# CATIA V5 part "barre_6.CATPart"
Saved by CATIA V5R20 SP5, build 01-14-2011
Part number: barre_6
Publications: "diamètre trou oblong 'd'", "diamètre trou oblong 'm'", "diamètre pivot en H"
Bounding box of the stored display mesh (mm): x 12 to 18, y -56 to -29.216, z 65.601 to 246.824
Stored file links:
  M:\EU_thinkMotion\IAO_2010\iao\IAO_MMS_Groupe2\IAO_MMS_Groupe2\sdubois\sdubois\sdubois\IAO_mecanisme\barre_6.CATPart
  M:\EU_thinkMotion\IAO_2010\iao\IAO_MMS_Groupe2\IAO_MMS_Groupe2\sdubois\sdubois\sdubois\IAO_mecanisme\assembage final.CATProduct
  M:\EU_thinkMotion\IAO_2010\iao\IAO_MMS_Groupe2\IAO_MMS_Groupe2\sdubois\sdubois\sdubois\IAO_mecanisme\squelette_6.CATPart
  M:\EU_thinkMotion\IAO_2010\iao\IAO_MMS_Groupe2\IAO_MMS_Groupe2\sdubois\sdubois\sdubois\IAO_mecanisme\bati_0.CATPart
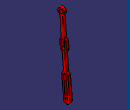
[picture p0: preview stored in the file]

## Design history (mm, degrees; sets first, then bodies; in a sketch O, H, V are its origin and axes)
Parameters
  `diamètre trou oblong 'd'` = 6 mm
  `diamètre trou oblong 'm'` = 8 mm
  `diamètre pivot en H` = 8 mm
External parameters (linked from other documents)
  External.largeur_barre = 6 mm
Set1
  Plane1: linked copy from another document
  Plane2: linked copy from another document
  Point1: linked copy from another document
  Point2: linked copy from another document
  Plane3: linked copy from another document
  Plane4: linked copy from another document
  Point3 to Point7: linked copy from another document
  Plane5 to Plane7: linked copy from another document
  DatumSurface1: linked copy from another document
  Line1 to Line5: linked copy from another document
Body1 (main body)
  Sketch1 on Plane1, origin (12, 0, 0), H (0, 1, 0), V (0, 0, 1)
    line L1 (-39.207, 72.2588) -> (-51.9913, 239.7717)
    point P1 (-39.207, 72.2588)
    point P2 (-51.9913, 239.7717)
    line L2 (-33.2244, 72.7154) -> (-46.0087, 240.2283)
    point P3 (-33.2244, 72.7154)
    point P4 (-46.0087, 240.2283)
    line L3 (-51.9913, 239.7717) -> (-46.0087, 240.2283)
    point P5 (-51.9913, 239.7717)
    point P6 (-46.0087, 240.2283)
    point P7 (-39.207, 72.2588)
    reference intersected line E1 through (-30.489, -2.55) direction (0.0761, -0.9971) from Plane2
    reference intersected line E2 through (-30.489, -2.55) direction (0.0761, -0.9971) from Plane2
    reference projected point E3 (-46.6645, 169.9747) from Point1
    reference projected point E4 (-40.6819, 170.4313) from Point2
    reference intersected line E5 through (-6.293, 74.7708) direction (-0.9971, -0.0761) from Plane3
    reference intersected line E6 through (-6.293, 74.7708) direction (-0.9971, -0.0761) from Plane3
    reference intersected line E7 through (-20.3417, 242.1871) direction (-0.9971, -0.0761) from Plane4
    reference intersected line E8 through (-20.3417, 242.1871) direction (-0.9971, -0.0761) from Plane4
    line L4 (-39.207, 72.2588) -> (-33.2244, 72.7154)
    point P8 (-39.207, 72.2588)
    point P9 (-33.2244, 72.7154)
    distance L1 E3 = 0
    distance L2 E4 = 0
    distance P1 E5 = 0
    distance P3 E6 = 0
    distance P2 E7 = 0
    distance P4 E8 = 0
    distance P5 P2 = 0
    distance P6 P4 = 0
    distance P1 P7 = 0
    distance P8 P1 = 0
    distance P9 P3 = 0
    parallelism: L1 E1, L2 E2
  Sketch2 on Plane1, origin (12, 0, 0), H (0, 1, 0), V (0, 0, 1)
    circle A1 centre (-36.2157, 72.4871) radius 7
    point P1 (-36.2157, 72.4871)
    circle A2 centre (-43.6732, 170.203) radius 7
    point P2 (-43.6732, 170.203)
    circle A3 centre (-39.8684, 120.3479) radius 7
    point P3 (-39.8684, 120.3479)
    circle A4 centre (-44.7386, 184.1624) radius 7
    point P4 (-44.7386, 184.1624)
    reference projected point E1 (-36.2157, 72.4871) from Point3
    reference projected point E2 (-39.8684, 120.3479) from Point4
    reference projected point E3 (-43.6732, 170.203) from Point5
    reference projected point E4 (-44.7386, 184.1624) from Point6
    circle A5 centre (-49, 240) radius 7
    point P5 (-49, 240)
    reference projected point E5 (-49, 240) from Point7
    distance P1 E1 = 0
    radius A1 = 7
    distance P3 E2 = 0
    radius A3 = 7
    distance E3 P2 = 0
    radius A2 = 7
    distance P4 E4 = 0
    radius A4 = 7
    distance P5 E5 = 0
    radius A5 = 7
  Sketch3 on Plane1, origin (12, 0, 0), H (0, 1, 0), V (0, 0, 1)
    line L1 (-50.6529, 169.6703) -> (-51.7183, 183.6297)
    point P1 (-50.6529, 169.6703)
    point P2 (-51.7183, 183.6297)
    reference intersected line E1 through (-30.489, -2.55) direction (0.0761, -0.9971) from Plane2
    reference projected circle E2 centre (-43.6732, 170.203) radius 7 from Sketch2.A2
    reference intersected line E3 through (-15.6588, 186.3817) direction (-0.9971, -0.0761) from Plane5
    reference intersected line E4 through (-14.4881, 172.4303) direction (-0.9971, -0.0761) from Plane6
    line L2 (-36.6935, 170.7356) -> (-37.7589, 184.6951)
    point P3 (-36.6935, 170.7356)
    point P4 (-37.7589, 184.6951)
    reference intersected line E5 through (-30.489, -2.55) direction (0.0761, -0.9971) from Plane2
    reference projected circle E6 centre (-44.7386, 184.1624) radius 7 from Sketch2.A4
    reference intersected line E7 through (-15.6588, 186.3817) direction (-0.9971, -0.0761) from Plane5
    reference intersected line E8 through (-14.4881, 172.4303) direction (-0.9971, -0.0761) from Plane6
    line L3 (-51.7183, 183.6297) -> (-37.7589, 184.6951)
    point P5 (-51.7183, 183.6297)
    point P6 (-37.7589, 184.6951)
    line L4 (-50.6529, 169.6703) -> (-36.6935, 170.7356)
    point P7 (-50.6529, 169.6703)
    point P8 (-36.6935, 170.7356)
    line L5 (-29.236, 73.0198) -> (-32.8887, 120.8806)
    point P9 (-29.236, 73.0198)
    point P10 (-32.8887, 120.8806)
    line L6 (-43.1954, 71.9544) -> (-46.8481, 119.8153)
    point P11 (-43.1954, 71.9544)
    point P12 (-46.8481, 119.8153)
    reference intersected line E9 through (-30.489, -2.55) direction (0.0761, -0.9971) from Plane2
    reference intersected line E10 through (-30.489, -2.55) direction (0.0761, -0.9971) from Plane2
    reference projected circle E11 centre (-39.8684, 120.3479) radius 7 from Sketch2.A3
    reference projected circle E12 centre (-39.8684, 120.3479) radius 7 from Sketch2.A3
    reference intersected line E13 through (-6.293, 74.7708) direction (-0.9971, -0.0761) from Plane3
    reference intersected line E14 through (-10.3069, 122.604) direction (-0.9971, -0.0761) from Plane7
    reference intersected line E15 through (-6.293, 74.7708) direction (-0.9971, -0.0761) from Plane3
    reference intersected line E16 through (-10.3069, 122.604) direction (-0.9971, -0.0761) from Plane7
    line L7 (-46.8481, 119.8153) -> (-32.8887, 120.8806)
    point P13 (-46.8481, 119.8153)
    point P14 (-32.8887, 120.8806)
    line L8 (-43.1954, 71.9544) -> (-29.236, 73.0198)
    point P15 (-43.1954, 71.9544)
    point P16 (-29.236, 73.0198)
    distance L1 E2 = 0
    distance P2 E3 = 0
    distance P1 E4 = 0
    distance E6 L2 = 0
    distance P4 E7 = 0
    distance P3 E8 = 0
    distance P5 P2 = 0
    distance P6 P4 = 0
    distance P7 P1 = 0
    distance P8 P3 = 0
    distance L5 E11 = 0
    distance L6 E12 = 0
    distance P11 E13 = 0
    distance P12 E14 = 0
    distance P9 E15 = 0
    distance P10 E16 = 0
    distance P13 P12 = 0
    distance P14 P10 = 0
    distance P15 P11 = 0
    distance P16 P9 = 0
    parallelism: L1 E1, L2 E5, L5 E9, L6 E10
  Pad1: profile Sketch1, direction (1, 0, 0), length 6 {= 3*External.largeur_barre -12mm}, opposite side length 0 {= 12mm-2*External.largeur_barre}
  Pad2: profile Sketch2, direction (-1, 0, 0), length 0 {= 12mm-2*External.largeur_barre}, opposite side length 6 {= 3*External.largeur_barre -12mm}
  Pad3: profile Sketch3, direction (1, 0, 0), length 6 {= 3*External.largeur_barre -12mm}, opposite side length 0 {= 12mm-2*External.largeur_barre}
  Sketch4 on face of Pad3, origin (18, 0, 0), H (0, 1, 0), V (0, 0, 1)
    construction line L1 (-39.8684, 120.3479) -> (-36.2157, 72.4871)
    point P1 (-39.8684, 120.3479)
    point P2 (-36.2157, 72.4871)
    line L2 (-36.8771, 120.5762) -> (-33.2244, 72.7154)
    line L3 (-39.207, 72.2588) -> (-42.8597, 120.1197)
    arc A1 centre (-36.2157, 72.4871) radius 3 from (-33.2244, 72.7154) to (-39.207, 72.2588) cw
    arc A2 centre (-39.8684, 120.3479) radius 3 from (-42.8597, 120.1197) to (-36.8771, 120.5762) cw
    reference projected point E1 (-39.8684, 120.3479) from Line1
    reference projected point E2 (-36.2157, 72.4871) from Line2
    distance L1 L2 = 3 {= `diamètre trou oblong 'd'` /2}
    distance P1 E1 = 0
    distance P2 E2 = 0
    tangency: A1 L2, A2 L2, A1 L3, A2 L3
  Pocket1: profile Sketch4, direction (-1, 0, 0), length 6 {= External.largeur_barre}
  Sketch5 on face of Pad3, origin (18, 0, 0), H (0, 1, 0), V (0, 0, 1)
    construction line L1 (-44.7386, 184.1624) -> (-43.6732, 170.203)
    point P1 (-44.7386, 184.1624)
    point P2 (-43.6732, 170.203)
    line L2 (-40.7502, 184.4668) -> (-39.6848, 170.5074)
    line L3 (-47.6616, 169.8986) -> (-48.727, 183.858)
    arc A1 centre (-43.6732, 170.203) radius 4 from (-39.6848, 170.5074) to (-47.6616, 169.8986) cw
    arc A2 centre (-44.7386, 184.1624) radius 4 from (-48.727, 183.858) to (-40.7502, 184.4668) cw
    reference projected point E1 (-44.7386, 184.1624) from Line3
    reference projected point E2 (-43.6732, 170.203) from Line4
    distance L1 L2 = 4 {= `diamètre trou oblong 'm'` /2}
    distance P1 E1 = 0
    distance P2 E2 = 0
    tangency: A1 L2, A2 L2, A1 L3, A2 L3
  Pocket2: profile Sketch5, direction (-1, 0, 0), length 6 {= External.largeur_barre}
  Sketch6 on face of Pad3, origin (18, 0, 0), H (0, 1, 0), V (0, 0, 1)
    circle A1 centre (-49, 240) radius 4
    point P1 (-49, 240)
    reference projected point E1 (-49, 240) from Line5
    distance P1 E1 = 0
    radius A1 = 4 {= `diamètre pivot en H` /2}
  Pocket3: profile Sketch6, direction (-1, 0, 0), length 6 {= External.largeur_barre}
  Sketch7 on face of Pad3, origin (18, 0, 0), H (0, 1, 0), V (0, 0, 1)
    line L1 (-44.7386, 184.1624) -> (-43.6732, 170.203)
    point P1 (-44.7386, 184.1624)
    point P2 (-43.6732, 170.203)
    line L2 (-39.8684, 120.3479) -> (-36.2157, 72.4871)
    point P3 (-39.8684, 120.3479)
    point P4 (-36.2157, 72.4871)
    reference projected arc E1 centre (-44.7386, 184.1624) radius 4 from (-40.7502, 184.4668) to (-48.727, 183.858) ccw from edge [face of Pad3 | face of Pocket2 from Sketch5.A2]
    reference projected arc E2 centre (-43.6732, 170.203) radius 4 from (-47.6616, 169.8986) to (-39.6848, 170.5074) ccw from edge [face of Pad3 | face of Pocket2 from Sketch5.A1]
    reference projected arc E3 centre (-39.8684, 120.3479) radius 3 from (-36.8771, 120.5762) to (-42.8597, 120.1197) ccw from edge [face of Pad3 | face of Pocket1 from Sketch4.A2]
    reference projected arc E4 centre (-36.2157, 72.4871) radius 3 from (-39.207, 72.2588) to (-33.2244, 72.7154) ccw from edge [face of Pad3 | face of Pocket1 from Sketch4.A1]
    distance P1 E1 = 4
    distance P2 E2 = 4
    distance P3 E3 = 3
    distance P4 E4 = 3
